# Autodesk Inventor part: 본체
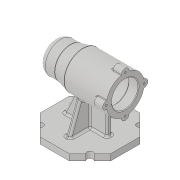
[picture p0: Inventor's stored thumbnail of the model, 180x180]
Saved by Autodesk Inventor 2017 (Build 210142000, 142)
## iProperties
Created: 2019-12
Part Number: 본체
Material: Generic
Document SubType Name: Modeling
Designer: 5-10-le
Density: 1 g/cm^3
Appearance: Default
Author: 5-10-le
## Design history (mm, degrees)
sketch "스케치1"
  geometry: 1 further point
sketch "스케치2"
  geometry: 1 further point
sketch "스케치3"
  geometry: L1 (-23.196, -56)-(-56, -23.196); L2 (-56, -23.196)-(-56, 23.196); L3 (-56, 23.196)-(-23.196, 56); L4 (-23.196, 56)-(23.196, 56); L5 (23.196, 56)-(56, 23.196); L6 (56, 23.196)-(56, -23.196); L7 (56, -23.196)-(23.196, -56); L8 (23.196, -56)-(-23.196, -56); L9 (0, 0)-(71.034, 0); 2 further points
  constraints: 18 end point, 1 horizontal, 1 midpoint, 17 other
extrude "돌출1" new body sketch "스케치3" distance "d2" = 10; taper "d3" = 0 deg
sketch "스케치4"
  geometry: L1 (-23.196, 56)-(-56, 23.196) reference; L2 (0, 0)-(-39.598, 39.598); L3 (0, 0)-(-91.826, 0); L4 (56, 23.196)-(23.196, 56) reference; L5 (-56, -23.196)-(-23.196, -56) reference; L6 (23.196, -56)-(56, -23.196) reference; L7 (39.598, 39.598)-(-39.598, -39.598); L8 (39.598, -39.598)-(0, 0); L9 (0, 0)-(79.196, 0); C1 r 5 at (-39.598, 39.598); C2 r 5 at (39.598, -39.598); C3 r 5 at (-39.598, -39.598); C4 r 5 at (39.598, 39.598); 2 further points
  constraints: 10 end point, 4 centre point, 4 midpoint, 2 coincident, 2 horizontal, 1 collinear, 1 perpendicular, 3 other
  dimensions: "d4" = 10 diameter of C1; "d7" = 10 diameter of C4; "d8" = 10 diameter of C3; "d9" = 10 diameter of C2
extrude "돌출2" cut sketch "스케치4" stored distance "d5" = 10; taper "d6" = 0 deg
sketch "스케치5"
  geometry: L1 (0, 0)-(0, 80); L2 (56, 0)-(56, 10) reference; L3 (56, 0)-(56, 80); L4 (-56, 80)-(56, 80); L5 (-56, 80)-(-56, 105); L6 (-11, 110)-(56, 110); L7 (-31, 105)-(-11, 110); L8 (-56, 105)-(-31, 105); L9 (56, 80)-(56, 110)
  constraints: 16 end point, 4 vertical, 2 parallel, 1 perpendicular
  dimensions: "d10" = 80 distance of L1.start L1.end; "d19" = 60 diameter of L6.start L4; "d20" = 50 diameter of L8 L4; "d21" = 25 distance from line of L7.start L5; "d22" = 45 distance from line of L6.start L5
revolve "회전1" sketch "스케치5" stored, may be unused: angle "d23" = 90 deg
fillet "모깎기1" dims "d24" = 10
sketch "스케치7"
  geometry: C1 r 30 at (0, 0) reference; C2 r 21 at (0, 0); 1 further point
  constraints: 1 centre point, 1 coincident
  dimensions: "d27" = 42 diameter of C2
extrude "돌출3" cut sketch "스케치7" distance "d28" = 15; taper "d29" = 0 deg
sketch "스케치8"
  geometry: C1 r 21 at (0, 0) reference; C2 r 24 at (0, 0); 1 further point
  constraints: 1 centre point, 1 coincident
  dimensions: "d30" = 48 diameter of C2
extrude "돌출4" cut sketch "스케치8" distance "d31" = 54; taper "d32" = 0 deg
sketch "스케치9"
  geometry: C1 r 24 at (0, 0) reference; C2 r 21 at (0, 0); 1 further point
  constraints: 1 centre point, 1 coincident
  dimensions: "d33" = 42 diameter of C2
extrude "돌출5" cut sketch "스케치9" distance "d34" = 12; taper "d35" = 0 deg
sketch "스케치10"
  geometry: C1 r 21 at (0, 0) reference; C2 r 17.5 at (0, 0); 1 further point
  constraints: 1 centre point, 1 coincident
  dimensions: "d36" = 35 diameter of C2
extrude "돌출6" cut sketch "스케치10" distance "d37" = 18; taper "d38" = 0 deg
sketch "스케치11"
  geometry: C1 r 17.5 at (0, 0) reference; C2 r 16 at (0, 0); 1 further point
  constraints: 1 centre point, 1 coincident
  dimensions: "d39" = 32 diameter of C2
extrude "돌출7" cut sketch "스케치11" distance "d40" = 4; taper "d41" = 0 deg
sketch "스케치12"
  geometry: C1 r 16 at (0, 0) reference; C2 r 10.5 at (0, 0); 1 further point
  constraints: 1 centre point, 1 coincident
  dimensions: "d42" = 21 diameter of C2
extrude "돌출8" cut sketch "스케치12" distance "d43" = 3; taper "d44" = 0 deg
sketch "스케치13"
  geometry: 1 further point
fillet "모깎기2" dims "d45" = 3
fillet "모깎기3" dims "d46" = 0.3
fillet "모깎기4" dims "d47" = 3
chamfer "모따기1" distance "d48" = 1; stored, may be unused: second distance "d49" = 2, angle "d50" = 45 deg
sketch "스케치14"
  geometry: C1 r 6 at (0, 30); 2 further points
  constraints: 1 centre point, 1 vertical alignment, 1 other
  dimensions: "d51" = 12 diameter of C1
extrude "돌출9" join sketch "스케치14" distance "d52" = 16; taper "d53" = 0 deg
fillet "모깎기5" dims "d54" = 3
fillet "모깎기6" dims "d55" = 1
sketch "스케치15"
  geometry: A1 r 6 centre (0, 0) between (5.998, 0.171) and (-5.998, 0.171) reference; A2 r 6 centre (-30, -30) between (-30.171, -24.002) and (-30.171, -35.998) reference; A3 r 6 centre (0, -60) between (-5.998, -60.171) and (5.998, -60.171) reference; A4 r 6 centre (30, -30) between (30.171, -35.998) and (30.171, -24.002) reference; 5 further points
  constraints: 4 coincident
hole "구멍1" sketch "스케치15" at (-30, -30), (0, 0), (30, -30), (0, -60) diameter "d59" = 3.242; stored, may be unused: countersink angle "d63" = 90 deg, drill point angle "d65" = 118 deg; dims "d60" = 8, "d61" = 4, "d62" = 2, "d64" = 11
sketch "스케치19"
  geometry: L1 (56, -23.196)-(56, 23.196) reference; L2 (0, -4)-(31, -4); L3 (31, -4)-(31, 4); L4 (31, 4)-(0, 4); L5 (2.576, 0.332)-(31, 4); L6 (31, -4)-(2.576, -0.332); L7 (0, 4)-(0, -4); 1 further point
  constraints: 12 end point, 2 point on line, 1 horizontal, 1 midpoint, 1 parallel, 1 perpendicular
  dimensions: "d77" = 8 distance of L2.end L3.end; "d78" = 25 distance from line of L1 L3.end
extrude "돌출10" join sketch "스케치19" stored distance "d79" = 8; taper "d80" = 0 deg
sketch "스케치20"
  geometry: L1 (-23.196, 10)-(-36.062, 10) reference; L2 (-56, 10)-(-43.134, 10) reference; L3 (-56, 0)-(-56, 10) reference; L4 (-31, 55)-(-11, 50) reference; L5 (-43.134, 10)-(-34.598, 10) reference; L6 (-11, 50)-(39, 50) reference; L7 (-31, 55)-(-31, 105) reference; L8 (-46, 105)-(-46, 55) reference; L9 (-23.196, 10)-(23.196, 10) reference; L10 (-36.062, 10)-(-36.062, 0) reference; L11 (-23.196, 0)-(-36.062, 0) reference; L12 (-23.196, 0)-(-23.196, 10) reference; L13 (-36.062, 10)-(-23.196, 10) reference; L14 (-43.134, 0)-(-43.134, 10) reference; L15 (-56, 10)-(-43.134, 10) reference; L16 (-56, 0)-(-56, 10) reference; L17 (-43.134, 0)-(-56, 0) reference; L18 (-31, 55)-(-11, 50) reference; L19 (-18.476, 51.869)-(-38, 10); L20 (-36.062, 10)-(-23.196, 10) reference; 1 further point
  constraints: 2 end point, 2 point on line
  dimensions: "d113" = 115 deg angle of L2 L19; "d114" = 18 distance from line of L16 L19.end
feature "리브1" sketch "스케치20" dims "d91" = 1, "d92" = 8, "d93" = 0, "d94" = 0, "d95" = 1, "d96" = 1
sketch "스케치21"
  geometry: L1 (10, 43.134)-(10, 34.598) reference; L2 (10, -23.196)-(10, 23.196) reference; L3 (10, 23.196)-(10, 36.062) reference; L4 (10, 43.134)-(10, 56) reference; L5 (56.766, 18.979)-(10, 36); L6 (0, 56)-(10, 56) reference; A1 r 30 centre (80, 0) between (56.766, 18.979) and (50.268, -4) reference; 2 further points
  constraints: 2 end point, 1 point on circle, 1 point on line
  dimensions: "d97" = 20 distance from line of L6 L5.end; "d98" = 110 deg angle of L4 L5
feature "리브2" sketch "스케치21" dims "d99" = 1, "d100" = 8, "d101" = 0, "d102" = 0, "d103" = 1, "d104" = 1
sketch "스케치22"
  geometry: L1 (10, -34.598)-(10, -43.134) reference; L2 (10, -36.062)-(10, -23.196) reference; L3 (10, -23.196)-(10, 23.196) reference; L4 (10, -56)-(10, -43.134) reference; L5 (56.766, -18.979)-(10, -36); L6 (0, -56)-(10, -56) reference; A1 r 30 centre (80, 0) between (56.766, -18.979) and (50.268, -4) reference; 2 further points
  constraints: 2 end point, 1 point on circle, 1 point on line
  dimensions: "d105" = 20 distance from line of L6 L5.end; "d106" = 110 deg angle of L4 L5
feature "리브3" sketch "스케치22" dims "d107" = 1, "d108" = 8, "d109" = 0, "d110" = 0, "d111" = 1, "d112" = 1
fillet "모깎기7" dims "d115" = 3
fillet "모깎기8" dims "d116" = 3
fillet "모깎기9" dims "d117" = 3
fillet "모깎기10" dims "d118" = 3
fillet "모깎기11" dims "d119" = 3
fillet "모깎기12" dims "d120" = 3
fillet "모깎기13" dims "d121" = 3
node "솔리드1"
pattern_circular "원형 패턴1" dims angle "d57" = 360 deg
node "투영된 루프1"
node "투영된 루프2"
node "투영된 루프3"
other parameters: "sa_0" = 4
